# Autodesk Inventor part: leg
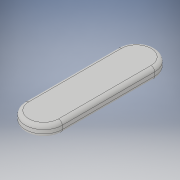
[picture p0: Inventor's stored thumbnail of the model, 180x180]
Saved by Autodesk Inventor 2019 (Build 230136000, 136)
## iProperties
Created: 2020-09
Part Number: leg
Material: 一般
Document SubType Name: Modeling
Designer: kikut
Density: 1 g/cm^3
Appearance: 既定
Author: kikut
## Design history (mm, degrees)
sketch "スケッチ1"
  geometry: L1 (-0.01, -0.05)-(0.01, -0.05); L2 (0.01, -0.05)-(0.01, 0); L3 (0.01, 0)-(-0.01, 0); L4 (-0.01, 0)-(-0.01, -0.05); L5 (-0.01, -0.05)-(0.01, 0); L6 (0.01, -0.05)-(-0.01, 0); L7 (0, -0.074)-(0, 0.024) reference; A1 r 0.01 centre (0, 0) between (0.01, 0) and (-0.01, 0); A2 r 0.01 centre (0, -0.05) between (-0.01, -0.05) and (0.01, -0.05); 2 further points
  constraints: 12 end point, 4 midpoint, 4 point on circle, 2 centre point, 2 parallel, 1 coincident, 1 horizontal, 1 perpendicular, 1 point on line, 1 other
  dimensions: "d0" = 0.02 distance of L2.end L3.end; "d1" = 0.05 distance of L1.end L2.end
extrude "押し出し1" new body sketch "スケッチ1" stored distance "d2" = 0.006; taper "d3" = 0 deg
fillet "フィレット1" dims "d4" = 0.002
node "ソリッド1"
